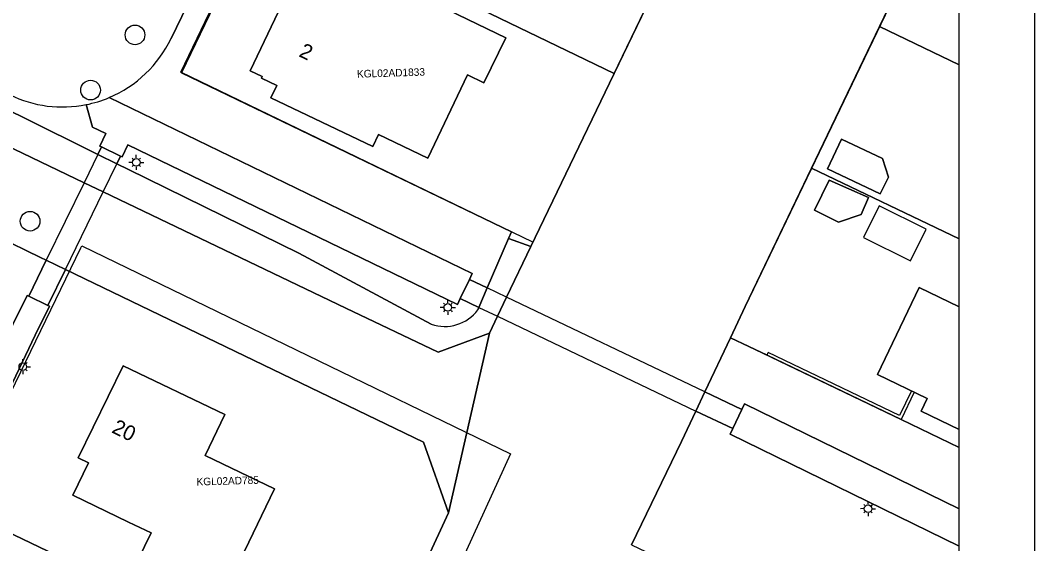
# Model space of a CAD drawing. Extents: x 124901 to 125496, y 515369 to 515789.
# Drawn here: x 125428.8 to 125495.9, y 515688.8 to 515723.4 of the extents above; entities that cross this region are included whole.
import ezdxf

# ---------------------------------------------------------------- set-up
doc = ezdxf.new("R2010")
doc.units = 0
for name, color, linetype in [('Alg Kaders', 7, 'Continuous'), ('Brug', 7, 'Continuous'), ('Gebouw', 7, 'Continuous'), ('Lichtmast', 7, 'Continuous'), ('Onbegroeid terrein', 7, 'Continuous'), ('Overige bouwwerk', 7, 'Continuous'), ('Perceelnummers', 7, 'Continuous'), ('Perceelsgrenzen', 7, 'Continuous'), ('Putten', 7, 'Continuous'), ('Scheiding', 7, 'Continuous'), ('Teksten', 7, 'Continuous'), ('Vegetatie', 7, 'Continuous'), ('Voetpad', 7, 'Continuous'), ('Water', 7, 'Continuous'), ('Wegen lokale weg', 7, 'Continuous')]:
    doc.layers.add(name, color=color, linetype=linetype)

msp = doc.modelspace()

# ---------------------------------------------------------------- linework, layer by layer
at = {"layer": 'Alg Kaders'}
for points in [[(125495.925, 515789.043), (124901.425, 515789.043), (124901.425, 515368.543), (125495.925, 515368.543)], [(125490.925, 515784.043), (124906.425, 515784.043), (124906.425, 515373.543), (125490.925, 515373.543)]]:
    msp.add_lwpolyline(points, close=True, dxfattribs=at)
at = {"layer": 'Brug'}
for points in [[(125435.447, 515714.407), (125434.186, 515715.023), (125433.943, 515714.525), (125433.028, 515712.65), (125430.529, 515707.53), (125429.368, 515705.152), (125430.629, 515704.536), (125431.793, 515706.92), (125434.294, 515712.044), (125435.2, 515713.901)], [(125457.922, 515704.994), (125459.148, 515704.409), (125460.38, 515703.822), (125473.512, 515697.555), (125475.946, 515696.393), (125476.551, 515697.66), (125474.11, 515698.825), (125460.986, 515705.088), (125459.704, 515705.7), (125458.527, 515706.261)]]:
    msp.add_lwpolyline(points, close=True, dxfattribs=at)
at = {"layer": 'Gebouw'}
for points in [[(125445.793, 515719.077), (125445.396, 515718.274), (125452.124, 515715.039), (125452.514, 515715.85), (125455.767, 515714.286), (125458.406, 515719.776), (125459.488, 515719.252), (125460.923, 515722.237), (125450.736, 515727.164), (125450.732, 515727.166), (125449.352, 515724.421), (125448.194, 515724.976), (125447.53, 515725.294), (125446.933, 515724.054), (125446.122, 515724.444), (125444.011, 515720.049), (125444.814, 515719.669), (125444.773, 515719.572)], [(125482.21, 515713.564), (125485.698, 515711.928), (125486.261, 515713.019), (125485.865, 515714.261), (125483.137, 515715.541)], [(125482.33, 515712.813), (125481.347, 515710.829), (125482.934, 515710.043), (125484.435, 515710.556), (125484.926, 515711.683)], [(125433.312, 515694.13), (125432.28, 515692), (125435.972, 515690.217), (125437.458, 515689.5), (125436.149, 515686.79), (125441.65, 515684.17), (125445.627, 515692.406), (125441.046, 515694.619), (125442.35, 515697.32), (125435.61, 515700.54), (125432.65, 515694.45)]]:
    msp.add_lwpolyline(points, close=True, dxfattribs=at)
msp.add_lwpolyline([(125490.925, 515704.455), (125488.285, 515705.714), (125485.521, 515699.972), (125488.814, 515698.391), (125488.408, 515697.546), (125490.925, 515696.337)], dxfattribs=at)
at = {"layer": 'Lichtmast'}
for p, q in [((125436.273, 515714.21), (125436.203, 515714.281)), ((125436.485, 515714.298), (125436.485, 515714.498)), ((125436.697, 515714.21), (125436.768, 515714.282)), ((125436.185, 515713.999), (125435.985, 515713.998)), ((125436.273, 515713.786), (125436.201, 515713.715)), ((125436.485, 515713.698), (125436.485, 515713.498)), ((125436.697, 515713.786), (125436.767, 515713.715)), ((125436.785, 515713.998), (125436.985, 515713.998)), ((125456.883, 515704.62), (125456.813, 515704.691)), ((125457.095, 515704.708), (125457.095, 515704.908)), ((125457.307, 515704.62), (125457.378, 515704.692)), ((125456.795, 515704.409), (125456.595, 515704.408)), ((125456.883, 515704.196), (125456.811, 515704.125)), ((125457.095, 515704.108), (125457.095, 515703.908)), ((125457.307, 515704.196), (125457.377, 515704.125)), ((125457.395, 515704.408), (125457.595, 515704.408)), ((125428.976, 515700.789), (125428.976, 515700.989)), ((125429.188, 515700.701), (125429.259, 515700.773)), ((125428.976, 515700.189), (125428.976, 515699.989)), ((125429.188, 515700.277), (125429.258, 515700.206)), ((125429.276, 515700.489), (125429.476, 515700.489)), ((125484.687, 515691.311), (125484.617, 515691.382)), ((125484.899, 515691.399), (125484.899, 515691.599)), ((125485.111, 515691.311), (125485.182, 515691.383)), ((125484.599, 515691.1), (125484.399, 515691.099)), ((125484.687, 515690.887), (125484.615, 515690.816)), ((125484.899, 515690.799), (125484.899, 515690.599)), ((125485.111, 515690.887), (125485.181, 515690.816)), ((125485.199, 515691.099), (125485.399, 515691.099))]:
    msp.add_line(p, q, dxfattribs=at)
for centre in [(125436.485, 515713.998), (125457.095, 515704.408), (125428.976, 515700.489), (125484.899, 515691.099)]:
    msp.add_circle(centre, 0.25, dxfattribs=at)
at = {"layer": 'Onbegroeid terrein'}
for points in [[(125470.178, 515784.043), (125469.041, 515781.795), (125465.136, 515773.418), (125463.143, 515769.319), (125462.318, 515767.59), (125460.37, 515763.52), (125456.171, 515754.701), (125454.205, 515750.585), (125453.358, 515748.9), (125451.403, 515744.791), (125447.298, 515736.218), (125445.324, 515732.123), (125444.512, 515730.405), (125442.553, 515726.333), (125439.467, 515719.919), (125461.302, 515709.415), (125461.108, 515708.964), (125462.592, 515708.439), (125490.925, 515767.272)], [(125490.925, 515733.941), (125476.768, 515704.472), (125475.792, 515702.399), (125478.214, 515701.239), (125487.081, 515696.994), (125490.925, 515695.153)], [(125452.441, 515680.669), (125457.131, 515690.833), (125455.479, 515695.495), (125431.793, 515706.92), (125430.629, 515704.536), (125430.732, 515704.484), (125429.798, 515702.583), (125421.887, 515685.97)], [(125490.925, 515696.337), (125488.408, 515697.546), (125488.814, 515698.391), (125485.521, 515699.972), (125488.285, 515705.714), (125490.925, 515704.455)]]:
    msp.add_lwpolyline(points, dxfattribs=at)
for points in [[(125445.396, 515718.274), (125445.793, 515719.077), (125444.773, 515719.572), (125444.814, 515719.669), (125444.011, 515720.049), (125446.122, 515724.444), (125446.933, 515724.054), (125447.53, 515725.294), (125448.194, 515724.976), (125449.352, 515724.421), (125450.732, 515727.166), (125450.736, 515727.164), (125460.923, 515722.237), (125459.488, 515719.252), (125458.406, 515719.776), (125455.767, 515714.286), (125452.514, 515715.85), (125452.124, 515715.039)], [(125485.698, 515711.928), (125482.21, 515713.564), (125483.137, 515715.541), (125485.865, 515714.261), (125486.261, 515713.019)], [(125433.943, 515714.525), (125435.2, 515713.901), (125435.447, 515714.407), (125434.186, 515715.023)], [(125482.33, 515712.813), (125484.926, 515711.683), (125484.435, 515710.556), (125482.934, 515710.043), (125481.347, 515710.829)], [(125431.793, 515706.92), (125430.529, 515707.53), (125429.368, 515705.152), (125430.629, 515704.536)], [(125459.148, 515704.409), (125459.704, 515705.7), (125458.527, 515706.261), (125457.922, 515704.994)], [(125432.28, 515692), (125433.312, 515694.13), (125432.65, 515694.45), (125435.61, 515700.54), (125442.35, 515697.32), (125441.046, 515694.619), (125445.627, 515692.406), (125441.65, 515684.17), (125436.149, 515686.79), (125437.458, 515689.5), (125435.972, 515690.217)], [(125474.11, 515698.825), (125473.512, 515697.555), (125475.946, 515696.393), (125476.551, 515697.66)]]:
    msp.add_lwpolyline(points, close=True, dxfattribs=at)
at = {"layer": 'Overige bouwwerk'}
msp.add_lwpolyline([(125485.626, 515711.117), (125484.596, 515709.034), (125487.714, 515707.491), (125488.745, 515709.575)], close=True, dxfattribs=at)
at = {"layer": 'Perceelsgrenzen'}
for points in [[(125490.925, 515767.272), (125490.581, 515766.558), (125486.079, 515757.21), (125481.589, 515747.886), (125477.083, 515738.53), (125472.603, 515729.228), (125468.102, 515719.881), (125462.723, 515708.711), (125439.425, 515719.965), (125444.794, 515731.147), (125449.264, 515740.456), (125453.764, 515749.828), (125458.221, 515759.111), (125462.706, 515768.452), (125467.174, 515777.757), (125470.192, 515784.043)], [(125490.925, 515695.153), (125475.792, 515702.398), (125476.768, 515704.472), (125481.16, 515713.614), (125485.656, 515722.973), (125490.15, 515732.328), (125490.925, 515733.941)], [(125490.925, 515720.447), (125485.656, 515722.973), (125490.15, 515732.328), (125490.925, 515731.956)], [(125490.925, 515708.934), (125481.16, 515713.614), (125485.656, 515722.973), (125490.925, 515720.447)], [(125490.925, 515695.153), (125475.792, 515702.398), (125476.768, 515704.472), (125481.16, 515713.614), (125490.925, 515708.934)], [(125422.606, 515687.317), (125424.5, 515691.221), (125432.811, 515708.356), (125432.874, 515708.485), (125461.248, 515694.727), (125453.316, 515677.409)]]:
    msp.add_lwpolyline(points, dxfattribs=at)
for points in [[(125472.603, 515729.228), (125468.102, 515719.881), (125444.794, 515731.147), (125449.264, 515740.456), (125452.96, 515738.684), (125464.804, 515732.977)], [(125462.723, 515708.711), (125439.425, 515719.965), (125444.794, 515731.147), (125468.102, 515719.881)], [(125453.316, 515677.409), (125424.5, 515691.221), (125432.811, 515708.356), (125432.874, 515708.485), (125461.248, 515694.727)], [(125417.983, 515677.745), (125422.606, 515687.317), (125424.5, 515691.221), (125453.316, 515677.409), (125452.553, 515675.743), (125446.912, 515663.647)]]:
    msp.add_lwpolyline(points, close=True, dxfattribs=at)
at = {"layer": 'Putten'}
for centre in [(125436.4, 515722.43), (125433.46, 515718.78), (125429.46, 515710.11)]:
    msp.add_circle(centre, 0.65, dxfattribs=at)
at = {"layer": 'Scheiding'}
for points in [[(125478.214, 515701.239), (125478.3, 515701.419)], [(125487.765, 515698.895), (125486.987, 515697.261), (125478.3, 515701.419)], [(125487.081, 515696.994), (125478.214, 515701.239)], [(125487.945, 515698.808), (125487.081, 515696.994)]]:
    msp.add_lwpolyline(points, dxfattribs=at)
at = {"layer": 'Vegetatie'}
for points in [[(125377.122, 515742.613), (125377.049, 515742.622), (125376.976, 515742.63), (125376.683, 515742.027), (125377.295, 515741.756), (125383.764, 515738.671), (125428.849, 515717.056), (125433.943, 515714.525), (125434.186, 515715.023), (125434.079, 515715.075), (125434.469, 515715.912), (125433.579, 515716.337), (125433.163, 515717.815)], [(125461.302, 515709.415), (125439.467, 515719.919), (125442.553, 515726.333), (125441.544, 515726.832)], [(125440.934, 515726.623), (125438.785, 515722.195)], [(125434.695, 515718.285), (125458.717, 515706.66), (125458.527, 515706.261), (125459.704, 515705.7), (125461.108, 515708.964), (125461.302, 515709.415)], [(125457.74, 515704.611), (125435.917, 515715.16), (125435.544, 515714.366), (125435.447, 515714.407), (125435.2, 515713.901), (125435.967, 515713.52), (125447.229, 515707.992), (125456.003, 515703.306)], [(125459.079, 515704.248), (125459.148, 515704.409), (125457.922, 515704.994), (125457.74, 515704.611)], [(125490.925, 515695.153), (125487.081, 515696.994), (125478.214, 515701.239), (125475.792, 515702.399), (125474.11, 515698.825), (125476.551, 515697.66), (125476.732, 515698.039), (125490.925, 515691.099)], [(125490.925, 515688.612), (125475.767, 515696.017), (125475.946, 515696.393), (125473.512, 515697.555), (125472.559, 515695.531), (125469.241, 515688.71), (125471.651, 515687.572), (125476.961, 515685.064), (125480.14, 515683.538), (125490.925, 515678.324)]]:
    msp.add_lwpolyline(points, dxfattribs=at)
msp.add_lwpolyline([(125424.616, 515705.029), (125425.14, 515704.782), (125428.111, 515703.379), (125428.315, 515703.282), (125429.265, 515705.202), (125429.368, 515705.152), (125430.529, 515707.53), (125430.152, 515707.712), (125427.225, 515709.124), (125424.481, 515710.447), (125422.352, 515706.097)], close=True, dxfattribs=at)
for centre, radius, start, end in [((125431.57, 515725.648), 7.999, 292.99768, 334.42444), ((125431.606, 515725.597), 7.937, 243.98431, 281.31237), ((125456.905, 515705.855), 2.704, 250.52345, 323.53012)]:
    msp.add_arc(centre, radius, start, end, dxfattribs=at)
at = {"layer": 'Voetpad'}
for points in [[(125435.544, 515714.366), (125435.917, 515715.16), (125457.74, 515704.611), (125457.922, 515704.994), (125458.527, 515706.261), (125458.717, 515706.66), (125434.695, 515718.285)], [(125433.163, 515717.815), (125433.579, 515716.337), (125434.469, 515715.912), (125434.079, 515715.075), (125434.186, 515715.023), (125435.447, 515714.407), (125435.544, 515714.366)], [(125372.6, 515642.854), (125381.355, 515645.99), (125389.202, 515648.653), (125406.911, 515654.851), (125412.818, 515667.163), (125421.887, 515685.97), (125429.798, 515702.583), (125430.732, 515704.484), (125430.629, 515704.536), (125429.368, 515705.152), (125429.265, 515705.202), (125428.315, 515703.282), (125420.361, 515686.071), (125414.125, 515673.202), (125405.801, 515656.14), (125390.738, 515650.782), (125379.528, 515646.88), (125378.796, 515648.945), (125374.603, 515647.262)], [(125490.925, 515691.099), (125476.732, 515698.039), (125476.551, 515697.66), (125475.946, 515696.393), (125475.767, 515696.017), (125490.925, 515688.612)]]:
    msp.add_lwpolyline(points, dxfattribs=at)
for points in [[(125431.793, 515706.92), (125434.294, 515712.044), (125435.2, 515713.901), (125435.447, 515714.407), (125434.186, 515715.023), (125433.943, 515714.525), (125433.028, 515712.65), (125430.529, 515707.53), (125429.368, 515705.152), (125430.629, 515704.536)], [(125458.527, 515706.261), (125457.922, 515704.994), (125459.148, 515704.409), (125460.38, 515703.822), (125473.512, 515697.555), (125475.946, 515696.393), (125476.551, 515697.66), (125474.11, 515698.825), (125460.986, 515705.088), (125459.704, 515705.7)]]:
    msp.add_lwpolyline(points, close=True, dxfattribs=at)
msp.add_arc((125431.572, 515725.732), 8.075, 281.36106, 292.74977, dxfattribs=at)
at = {"layer": 'Water'}
for points in [[(125490.925, 515767.272), (125462.592, 515708.439), (125460.986, 515705.088), (125460.38, 515703.822), (125459.845, 515702.706), (125457.131, 515690.833), (125452.441, 515680.669)], [(125456.003, 515703.306), (125447.229, 515707.992), (125435.967, 515713.52), (125435.2, 515713.901), (125433.943, 515714.525), (125428.849, 515717.056), (125383.764, 515738.671), (125377.295, 515741.756), (125376.241, 515739.601), (125423.743, 515717.088), (125433.028, 515712.65), (125434.294, 515712.044), (125450.353, 515704.367), (125456.457, 515701.452), (125459.845, 515702.706), (125460.38, 515703.822), (125460.986, 515705.088), (125462.592, 515708.439), (125461.108, 515708.964), (125459.704, 515705.7)], [(125469.241, 515688.71), (125472.559, 515695.531), (125473.512, 515697.555), (125474.11, 515698.825), (125475.792, 515702.399), (125476.768, 515704.472), (125490.925, 515733.941)], [(125459.704, 515705.7), (125459.148, 515704.409), (125459.079, 515704.248)]]:
    msp.add_lwpolyline(points, dxfattribs=at)
msp.add_lwpolyline([(125434.294, 515712.044), (125433.028, 515712.65), (125423.743, 515717.088), (125376.241, 515739.601), (125373.683, 515734.37), (125408.558, 515717.624), (125423.853, 515710.375), (125424.391, 515710.491), (125424.481, 515710.447), (125427.225, 515709.124), (125430.152, 515707.712), (125430.529, 515707.53), (125431.793, 515706.92), (125455.479, 515695.495), (125457.131, 515690.833), (125459.845, 515702.706), (125456.457, 515701.452), (125450.353, 515704.367)], close=True, dxfattribs=at)
msp.add_arc((125456.905, 515705.855), 2.704, 250.52345, 323.53012, dxfattribs=at)
at = {"layer": 'Wegen lokale weg'}
msp.add_lwpolyline([(125438.785, 515722.195), (125440.934, 515726.623), (125443.271, 515731.487), (125443.277, 515731.499), (125443.715, 515732.413), (125443.734, 515732.452), (125446.046, 515737.263), (125446.066, 515737.305), (125449.794, 515745.094), (125452.151, 515749.997), (125452.576, 515750.879), (125452.594, 515750.916), (125454.914, 515755.801), (125458.759, 515763.761), (125458.761, 515763.765), (125461.091, 515768.655)], dxfattribs=at)
for centre, radius, start, end in [((125431.57, 515725.648), 7.999, 292.99768, 334.42444), ((125431.606, 515725.597), 7.937, 243.98431, 281.31237), ((125431.572, 515725.732), 8.075, 281.36106, 292.74977)]:
    msp.add_arc(centre, radius, start, end, dxfattribs=at)

# ---------------------------------------------------------------- texts
at = {"layer": 'Perceelnummers'}
for s, rotation, p in [('KGL02AD1833', 1.83333, (125451.094, 515719.594)), ('KGL02AD785', 1.63501, (125440.476, 515692.628))]:
    msp.add_text(s, height=0.5, rotation=rotation, dxfattribs=at).set_placement(p)
at = {"layer": 'Teksten'}
for s, rotation, p in [('2', 334.3, (125447.183, 515721.034)), ('20', 334.1, (125434.798, 515696.158))]:
    msp.add_text(s, height=1, rotation=rotation, dxfattribs=at).set_placement(p)

doc.saveas('drawing.dxf')
